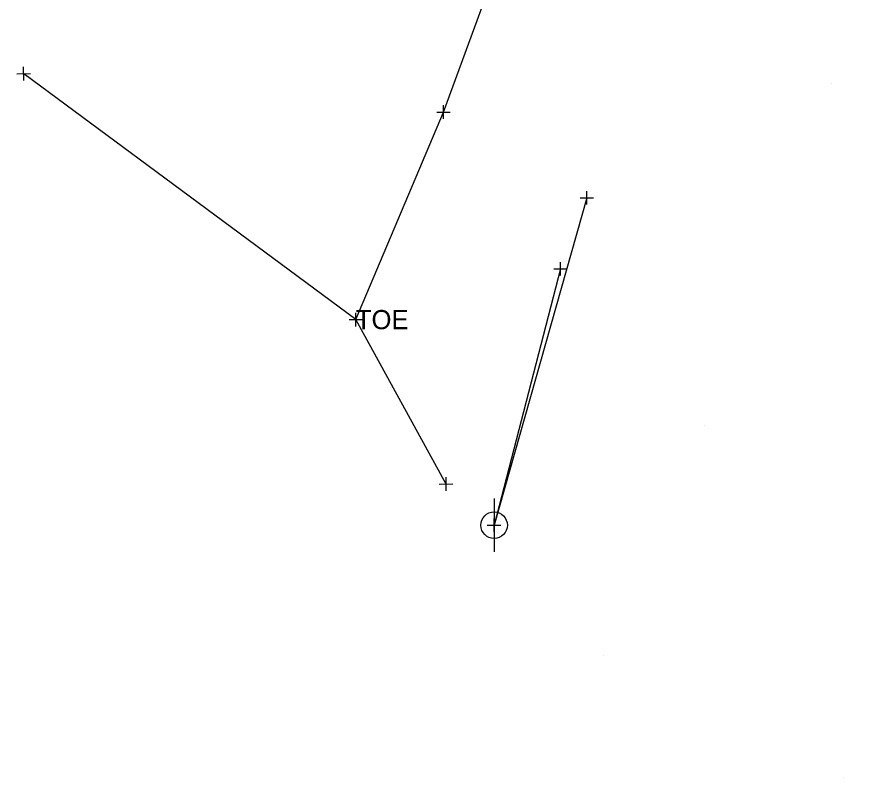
# Model space of a CAD drawing. Extents: x 1738496 to 1739092, y 463766 to 465141.
# Drawn here: x 1738787.6 to 1738867, y 464801.3 to 464872.7 of the extents above; entities that cross this region are included whole.
import ezdxf

# ---------------------------------------------------------------- set-up
doc = ezdxf.new("R2010")
doc.units = 0
for name, color, linetype in [('Default', 7, 'Continuous'), ('S_Survey_Shot', 7, 'Continuous'), ('S_Terrain_Breaklines', 7, 'Continuous'), ('S_Terrain_High_Points', 7, 'Continuous'), ('S_Terrain_Low_Points', 7, 'Continuous'), ('S_Terrain_Minor_Contours', 7, 'Continuous'), ('S_Terrain_Triangles', 7, 'Continuous'), ('S_Terrain_XSC', 7, 'Continuous')]:
    doc.layers.add(name, color=color, linetype=linetype)

msp = doc.modelspace()

# ---------------------------------------------------------------- linework, layer by layer
at = {"layer": 'Default'}
for p, q in [((1738832.398, 464824.987), (1738832.406, 464824.994)), ((1738832.406, 464824.987), (1738832.398, 464824.994)), ((1738832.402, 464824.991), (1738832.402, 464824.991))]:
    msp.add_line(p, q, dxfattribs=at)
msp.add_circle((1738832.402, 464824.991), 0.00528, dxfattribs=at)
at = {"layer": 'S_Terrain_Breaklines'}
msp.add_lwpolyline([(1738827.889, 464828.862), (1738819.416, 464844.301), (1738788.206, 464867.4)], dxfattribs=at)
at = {"layer": 'S_Terrain_High_Points'}
for points in [[(1738841.116, 464855.738), (1738832.402, 464824.991)], [(1738838.643, 464849.068), (1738832.402, 464824.991)]]:
    msp.add_lwpolyline(points, dxfattribs=at)
at = {"layer": 'S_Terrain_Low_Points'}
msp.add_lwpolyline([(1738819.416, 464844.301), (1738827.653, 464863.798), (1738840.339, 464898.356), (1738852.673, 464935.538), (1738872.139, 464968.856), (1738851.186, 464980.059)], dxfattribs=at)
at = {"layer": 'S_Terrain_Minor_Contours'}
msp.add_line((1738832.402, 464827.486), (1738832.402, 464822.496), dxfattribs=at)
msp.add_circle((1738832.402, 464824.991), 1.248, dxfattribs=at)
at = {"layer": 'S_Terrain_Triangles'}
for p, q in [((1738864.072, 464866.433), (1738864.072, 464866.433)), ((1738852.188, 464834.388), (1738852.188, 464834.388)), ((1738842.686, 464812.749), (1738842.686, 464812.749)), ((1738865.238, 464801.335), (1738865.238, 464801.335))]:
    msp.add_line(p, q, dxfattribs=at)
at = {"layer": 'S_Terrain_XSC'}
for p, q in [((1738787.57, 464867.399), (1738788.842, 464867.402)), ((1738788.207, 464866.764), (1738788.205, 464868.037)), ((1738788.206, 464867.4), (1738788.206, 464867.4)), ((1738827.654, 464863.162), (1738827.652, 464864.434)), ((1738827.017, 464863.797), (1738828.289, 464863.799)), ((1738827.653, 464863.798), (1738827.653, 464863.798)), ((1738841.117, 464855.102), (1738841.114, 464856.374)), ((1738840.479, 464855.737), (1738841.752, 464855.74)), ((1738841.116, 464855.738), (1738841.116, 464855.738)), ((1738838.007, 464849.067), (1738839.279, 464849.07)), ((1738838.644, 464848.432), (1738838.641, 464849.705)), ((1738838.643, 464849.068), (1738838.643, 464849.068)), ((1738818.779, 464844.3), (1738820.052, 464844.302)), ((1738818.779, 464844.3), (1738820.052, 464844.302)), ((1738819.417, 464843.665), (1738819.414, 464844.937)), ((1738819.417, 464843.665), (1738819.414, 464844.937)), ((1738819.416, 464844.301), (1738819.416, 464844.301)), ((1738819.416, 464844.301), (1738819.416, 464844.301)), ((1738827.891, 464828.225), (1738827.888, 464829.498)), ((1738827.253, 464828.86), (1738828.526, 464828.863)), ((1738827.889, 464828.862), (1738827.889, 464828.862)), ((1738832.403, 464824.354), (1738832.401, 464825.627)), ((1738832.403, 464824.354), (1738832.401, 464825.627)), ((1738831.766, 464824.989), (1738833.038, 464824.992)), ((1738831.766, 464824.989), (1738833.038, 464824.992)), ((1738832.402, 464824.991), (1738832.402, 464824.991)), ((1738832.402, 464824.991), (1738832.402, 464824.991))]:
    msp.add_line(p, q, dxfattribs=at)

# ---------------------------------------------------------------- texts
at = {"layer": 'S_Survey_Shot'}
msp.add_text('TOE', height=1.8, dxfattribs=at).set_placement((1738819.416, 464843.401))
msp.add_text('TOE', height=1.8, dxfattribs=at).set_placement((1738819.416, 464843.401))

doc.saveas('drawing.dxf')
